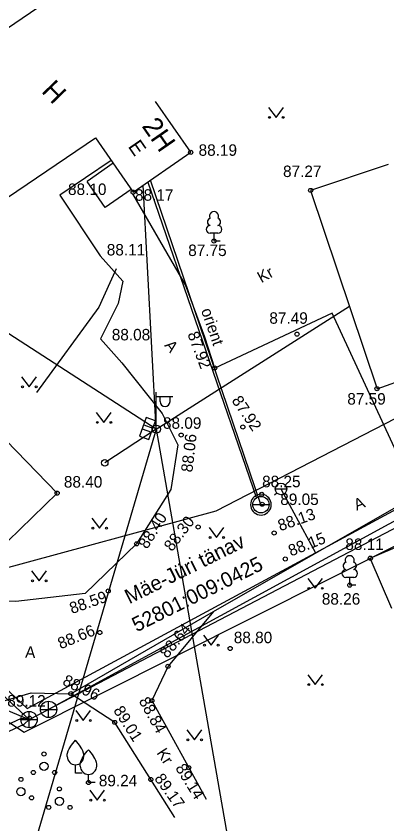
# Model space of a CAD drawing. Extents: x 648748 to 649126, y 6457789 to 6458252.
# Drawn here: x 649068.77 to 649091.37, y 6457945.81 to 6457995.06 of the extents above; entities that cross this region are included whole.
import ezdxf

# ---------------------------------------------------------------- set-up
doc = ezdxf.new("R2010")
doc.units = 0
for name, color, linetype in [('ELRAJATISMP', 7, 'Continuous'), ('HALJASTUS', 7, 'Continuous'), ('HOONE', 7, 'Continuous'), ('HOONEDET', 7, 'Continuous'), ('KKAEV', 7, 'Continuous'), ('KORGUS-EH2000', 7, 'Continuous'), ('KTRASS', 7, 'Continuous'), ('MPKAABEL', 7, 'Continuous'), ('MPOHULIIN', 7, 'Continuous'), ('PIIR', 7, 'Continuous'), ('POST', 7, 'Continuous'), ('PUU', 7, 'Continuous'), ('TEE', 7, 'Continuous'), ('VKAEV', 7, 'Continuous'), ('VTRASS', 7, 'Continuous')]:
    doc.layers.add(name, color=color, linetype=linetype)

msp = doc.modelspace()

# ---------------------------------------------------------------- linework, layer by layer
at = {"layer": 'ELRAJATISMP'}
for p, q in [((649076.706, 6457970.581), (649076.3, 6457969.457)), ((649077.268, 6457970.378), (649076.706, 6457970.581)), ((649076.861, 6457969.254), (649077.268, 6457970.378)), ((649076.457, 6457969.892), (649077.018, 6457969.689)), ((649076.549, 6457970.146), (649077.111, 6457969.943)), ((649076.3, 6457969.457), (649076.861, 6457969.254))]:
    msp.add_line(p, q, dxfattribs=at)
at = {"layer": 'HALJASTUS'}
for p, q in [((649084.161, 6457989.494), (649084.624, 6457988.888)), ((649084.624, 6457988.888), (649085.07, 6457989.494)), ((649069.102, 6457973.063), (649069.565, 6457972.457)), ((649069.565, 6457972.457), (649070.011, 6457973.063)), ((649073.66, 6457970.896), (649074.124, 6457970.29)), ((649074.124, 6457970.29), (649074.569, 6457970.896)), ((649073.394, 6457964.442), (649073.857, 6457963.835)), ((649073.857, 6457963.835), (649074.303, 6457964.442)), ((649080.531, 6457963.873), (649080.995, 6457963.266)), ((649080.995, 6457963.266), (649081.44, 6457963.873)), ((649069.706, 6457961.232), (649070.17, 6457960.626)), ((649070.17, 6457960.626), (649070.615, 6457961.232)), ((649086.548, 6457960.776), (649087.012, 6457960.17)), ((649087.012, 6457960.17), (649087.457, 6457960.776)), ((649080.196, 6457957.307), (649080.66, 6457956.7)), ((649080.66, 6457956.7), (649081.105, 6457957.307)), ((649086.548, 6457954.905), (649087.012, 6457954.298)), ((649087.012, 6457954.298), (649087.457, 6457954.905)), ((649072.403, 6457952.716), (649072.867, 6457952.11)), ((649072.867, 6457952.11), (649073.312, 6457952.716)), ((649079.182, 6457951.542), (649079.646, 6457950.935)), ((649079.646, 6457950.935), (649080.091, 6457951.542)), ((649073.257, 6457947.859), (649073.721, 6457947.252)), ((649073.721, 6457947.252), (649074.166, 6457947.859))]:
    msp.add_line(p, q, dxfattribs=at)
msp.add_lwpolyline([(649074.865, 6457979.646), (649073.818, 6457977.324), (649070.014, 6457972.105)], dxfattribs=at)
for centre in [(649084.223, 6457988.888), (649085.052, 6457988.888), (649069.164, 6457972.457), (649069.993, 6457972.457), (649073.723, 6457970.29), (649074.552, 6457970.29), (649073.456, 6457963.835), (649074.285, 6457963.835), (649080.594, 6457963.266), (649081.423, 6457963.266), (649069.769, 6457960.626), (649070.598, 6457960.626), (649086.611, 6457960.17), (649087.44, 6457960.17), (649080.259, 6457956.7), (649081.088, 6457956.7), (649086.611, 6457954.298), (649087.44, 6457954.298), (649072.466, 6457952.11), (649073.295, 6457952.11), (649079.245, 6457950.935), (649080.074, 6457950.935), (649073.32, 6457947.252), (649074.149, 6457947.252)]:
    msp.add_circle(centre, 0.055, dxfattribs=at)
at = {"layer": 'HOONE'}
for points in [[(649072.015, 6457996.882), (649063.446, 6457991.053), (649068.243, 6457984.001), (649073.604, 6457987.648), (649075.908, 6457984.326), (649079.415, 6457986.758), (649077.261, 6457989.865)], [(649091.46, 6457986.018), (649086.728, 6457984.435), (649090.775, 6457972.34), (649098.507, 6457975.105), (649096.333, 6457981.187)], [(649058.52, 6457968.558), (649063.804, 6457973.681), (649071.276, 6457965.976), (649065.991, 6457960.854), (649058.52, 6457968.558)], [(649091.683, 6457958.934), (649090.364, 6457962.006), (649093.978, 6457963.558), (649095.297, 6457960.486)]]:
    msp.add_lwpolyline(points, dxfattribs=at)
at = {"layer": 'HOONEDET'}
for p, q in [((649074.686, 6457986.087), (649073.096, 6457984.984)), ((649074.203, 6457983.387), (649073.096, 6457984.984)), ((649075.794, 6457984.49), (649074.203, 6457983.387))]:
    msp.add_line(p, q, dxfattribs=at)
at = {"layer": 'KKAEV'}
for p, q in [((649070.754, 6457952.286), (649070.754, 6457953.286)), ((649069.563, 6457951.663), (649069.563, 6457952.663)), ((649070.254, 6457952.786), (649071.254, 6457952.786)), ((649069.063, 6457952.163), (649070.063, 6457952.163))]:
    msp.add_line(p, q, dxfattribs=at)
for centre in [(649070.754, 6457952.786), (649069.563, 6457952.163)]:
    msp.add_circle(centre, 0.5, dxfattribs=at)
at = {"layer": 'KORGUS-EH2000'}
for centre in [(649079.415, 6457986.758), (649086.728, 6457984.435), (649075.908, 6457984.326), (649080.838, 6457981.344), (649085.896, 6457975.672), (649080.877, 6457973.605), (649090.775, 6457972.34), (649082.593, 6457970.01), (649078.835, 6457969.516), (649071.276, 6457965.976), (649083.748, 6457965.905), (649083.77, 6457965.298), (649079.871, 6457963.91), (649084.505, 6457963.542), (649076.118, 6457962.885), (649085.178, 6457961.959), (649090.364, 6457962.006), (649089.112, 6457960.362), (649074.389, 6457960.006), (649073.878, 6457957.474), (649081.822, 6457956.503), (649078.032, 6457955.416), (649072.111, 6457953.746), (649077.046, 6457953.323), (649069.586, 6457952.253), (649074.784, 6457951.992), (649079.298, 6457949.228), (649076.987, 6457948.512), (649073.186, 6457948.327)]:
    msp.add_circle(centre, 0.125, dxfattribs=at)
at = {"layer": 'KTRASS'}
for p, q in [((649044.701, 6457975.239), (649069.563, 6457952.163)), ((649069.563, 6457952.163), (649070.754, 6457952.786))]:
    msp.add_line(p, q, dxfattribs=at)
for points in [[(649110.189, 6457974.261), (649070.754, 6457952.786)], [(649096.029, 6457966.018), (649070.755, 6457952.79)], [(649051.71, 6457952.102), (649060.079, 6457956.155), (649069.563, 6457952.163)], [(649069.563, 6457952.163), (649069.086, 6457952.241), (649062.629, 6457949.241)], [(649062.797, 6457948.879), (649069.254, 6457951.879), (649069.563, 6457952.163)]]:
    msp.add_lwpolyline(points, dxfattribs=at)
at = {"layer": 'MPKAABEL'}
msp.add_line((649076.796, 6457984.942), (649083.432, 6457965.667), dxfattribs=at)
at = {"layer": 'MPOHULIIN'}
for q in [(649045.712, 6457990.322), (649076.524, 6457984.753), (649089.09, 6457977.375), (649069.137, 6457941.988), (649084.899, 6457926.464)]:
    msp.add_line((649077.318, 6457969.876), q, dxfattribs=at)
at = {"layer": 'PIIR'}
for p, q in [((649122.105, 6457986.094), (649080.95, 6457964.88)), ((649069.26, 6457951.39), (649125.584, 6457979.69)), ((649080.95, 6457964.88), (649065.03, 6457960.54)), ((649057.7, 6457959), (649069.26, 6457951.39))]:
    msp.add_line(p, q, dxfattribs=at)
at = {"layer": 'POST'}
for p, q in [((649077.318, 6457970.126), (649077.318, 6457972.126)), ((649077.318, 6457971.876), (649078.318, 6457971.876)), ((649077.545, 6457971.555), (649077.545, 6457971.876)), ((649078.158, 6457971.555), (649078.158, 6457971.876)), ((649077.318, 6457969.876), (649074.172, 6457967.817))]:
    msp.add_line(p, q, dxfattribs=at)
for centre, radius in [((649077.318, 6457969.876), 0.25), ((649074.172, 6457967.817), 0.2)]:
    msp.add_circle(centre, radius, dxfattribs=at)
msp.add_arc((649077.851, 6457971.555), 0.306, 180, 0, dxfattribs=at)
at = {"layer": 'PUU'}
for p, q in [((649081.078, 6457981.819), (649080.598, 6457981.819)), ((649080.838, 6457981.344), (649080.838, 6457981.819)), ((649081.218, 6457981.344), (649080.838, 6457981.344)), ((649089.352, 6457960.837), (649088.872, 6457960.837)), ((649089.112, 6457960.362), (649089.112, 6457960.837)), ((649089.492, 6457960.362), (649089.112, 6457960.362)), ((649072.393, 6457948.908), (649072.393, 6457949.408)), ((649072.793, 6457948.908), (649072.393, 6457948.908)), ((649073.186, 6457948.327), (649073.186, 6457948.827)), ((649073.586, 6457948.327), (649073.186, 6457948.327))]:
    msp.add_line(p, q, dxfattribs=at)
for points in [[(649071.893, 6457949.908), (649071.893, 6457950.058), (649071.903, 6457950.123), (649071.938, 6457950.253), (649071.998, 6457950.373), (649072.143, 6457950.608), (649072.303, 6457950.813), (649072.393, 6457950.908)], [(649072.893, 6457949.908), (649072.893, 6457950.058), (649072.883, 6457950.123), (649072.848, 6457950.253), (649072.788, 6457950.373), (649072.643, 6457950.608), (649072.483, 6457950.813), (649072.393, 6457950.908)], [(649072.686, 6457949.327), (649072.686, 6457949.477), (649072.696, 6457949.542), (649072.731, 6457949.672), (649072.791, 6457949.792), (649072.936, 6457950.027), (649073.096, 6457950.232), (649073.186, 6457950.327)], [(649073.686, 6457949.327), (649073.686, 6457949.477), (649073.676, 6457949.542), (649073.641, 6457949.672), (649073.581, 6457949.792), (649073.436, 6457950.027), (649073.276, 6457950.232), (649073.186, 6457950.327)]]:
    msp.add_lwpolyline(points, dxfattribs=at)
for centre, radius in [((649070.474, 6457950.067), 0.125), ((649070.474, 6457949.317), 0.25), ((649069.824, 6457948.942), 0.125), ((649071.124, 6457948.942), 0.125), ((649069.063, 6457948.519), 0.125), ((649069.063, 6457947.769), 0.25), ((649071.413, 6457947.936), 0.125), ((649069.713, 6457947.394), 0.125), ((649071.413, 6457947.186), 0.25), ((649070.763, 6457946.811), 0.125), ((649072.063, 6457946.811), 0.125)]:
    msp.add_circle(centre, radius, dxfattribs=at)
for centre, radius, start, end in [((649080.838, 6457982.864), 0.277, 332.58, 207.42), ((649080.668, 6457982.517), 0.233, 109.022, 253.142), ((649081.008, 6457982.517), 0.233, 286.851, 70.986), ((649080.601, 6457982.057), 0.238, 90.002, 269.395), ((649081.076, 6457982.057), 0.238, 270.605, 89.998), ((649089.112, 6457961.882), 0.277, 332.58, 207.42), ((649088.942, 6457961.535), 0.233, 109.022, 253.142), ((649089.282, 6457961.535), 0.233, 286.851, 70.986), ((649088.874, 6457961.075), 0.238, 90.002, 269.395), ((649089.349, 6457961.075), 0.238, 270.605, 89.998), ((649072.393, 6457949.908), 0.5, 180, 0), ((649073.186, 6457949.327), 0.5, 180, 0)]:
    msp.add_arc(centre, radius, start, end, dxfattribs=at)
at = {"layer": 'TEE'}
for points in [[(649073.892, 6457980.444), (649075.277, 6457978.898), (649074.998, 6457977.546), (649073.91, 6457975.39), (649075.219, 6457973.916), (649077.682, 6457970.841), (649078.634, 6457968.92), (649078.21, 6457966.199), (649076.118, 6457962.885), (649072.987, 6457959.848), (649068.76, 6457959.373), (649065.353, 6457959.385), (649062.208, 6457961.227), (649055.218, 6457967.101), (649039.374, 6457982.53), (649021.477, 6457999.638), (649003.487, 6458020.927), (649002.852, 6458022.042), (649010.237, 6458028.696), (649016.817, 6458021.893)], [(649024.176, 6457993.684), (649043.03, 6457975.251), (649059.66, 6457959.338), (649062.362, 6457955.934), (649067.734, 6457953.234), (649069.68, 6457953.796), (649072.111, 6457953.746), (649080.808, 6457958.747), (649093.109, 6457965.781), (649092.235, 6457967.901), (649088.043, 6457976.952), (649080.877, 6457973.605), (649080.278, 6457975.481), (649079.102, 6457978.684), (649075.883, 6457984.236)], [(649074.568, 6457986.256), (649071.44, 6457984.139), (649073.892, 6457980.444)], [(649080.808, 6457958.747), (649078.032, 6457955.416), (649077.046, 6457953.323), (649080.349, 6457947.317)], [(649078.453, 6457946.196), (649074.784, 6457951.992), (649072.111, 6457953.746)]]:
    msp.add_lwpolyline(points, dxfattribs=at)
at = {"layer": 'VKAEV'}
for p, q in [((649084.672, 6457965.983), (649084.532, 6457965.843)), ((649084.569, 6457966.23), (649085.269, 6457966.23)), ((649085.167, 6457965.983), (649085.306, 6457965.843)), ((649083.197, 6457965.273), (649084.197, 6457965.273))]:
    msp.add_line(p, q, dxfattribs=at)
msp.add_lwpolyline([(649084.329, 6457965.276), (649084.319, 6457965.386), (649084.29, 6457965.492), (649084.243, 6457965.592), (649084.179, 6457965.682), (649084.101, 6457965.759), (649084.01, 6457965.822), (649083.91, 6457965.868), (649083.803, 6457965.896), (649083.693, 6457965.905), (649083.584, 6457965.895), (649083.477, 6457965.866), (649083.378, 6457965.819), (649083.288, 6457965.755), (649083.21, 6457965.677), (649083.148, 6457965.586), (649083.102, 6457965.486), (649083.074, 6457965.379), (649083.065, 6457965.269), (649083.075, 6457965.16), (649083.104, 6457965.053), (649083.151, 6457964.954), (649083.215, 6457964.864), (649083.293, 6457964.786), (649083.384, 6457964.723), (649083.484, 6457964.677), (649083.591, 6457964.649), (649083.701, 6457964.64), (649083.81, 6457964.651), (649083.917, 6457964.68), (649084.016, 6457964.727), (649084.106, 6457964.791), (649084.184, 6457964.869), (649084.246, 6457964.96), (649084.292, 6457965.06), (649084.32, 6457965.166), (649084.329, 6457965.276)], dxfattribs=at)
for centre, radius in [((649084.919, 6457966.23), 0.35), ((649083.697, 6457965.273), 0.5)]:
    msp.add_circle(centre, radius, dxfattribs=at)
at = {"layer": 'VTRASS'}
msp.add_line((649083.697, 6457965.273), (649076.967, 6457985.06), dxfattribs=at)
for points in [[(648962.245, 6458064.485), (648962.49, 6458064.476), (648963.533, 6458062.388), (648984.937, 6458037.806), (648985.682, 6458036.975), (649020.474, 6457998.164), (649045.944, 6457974.832), (649068.737, 6457953.518), (649069.454, 6457952.848), (649087.021, 6457962.34), (649109.829, 6457974.665)], [(649084.92, 6457966.234), (649087.022, 6457962.344)]]:
    msp.add_lwpolyline(points, dxfattribs=at)

# ---------------------------------------------------------------- texts
at = {"layer": 'HOONE'}
for s, height, rotation, p in [('H', 1.2, 314.1017, (649070.264, 6457990.446)), ('2H', 1.2, 304.7389, (649076.403, 6457988.354)), ('E', 0.9, 304.7389, (649075.563, 6457987.114))]:
    msp.add_text(s, height=height, rotation=rotation, dxfattribs=at).set_placement(p)
at = {"layer": 'KORGUS-EH2000'}
for s, p in [('88.19', (649079.897, 6457986.545)), ('87.27', (649085.044, 6457985.25)), ('88.10', (649071.937, 6457984.156)), ('88.17', (649076.021, 6457983.804)), ('88.11', (649074.299, 6457980.467)), ('87.75', (649079.263, 6457980.434)), ('87.49', (649084.211, 6457976.303)), ('88.08', (649074.605, 6457975.289)), ('87.59', (649088.962, 6457971.374)), ('88.09', (649077.725, 6457969.899)), ('88.40', (649071.684, 6457966.314)), ('88.25', (649083.77, 6457966.334)), ('89.05', (649084.876, 6457965.251)), ('88.11', (649088.844, 6457962.509)), ('88.26', (649087.409, 6457959.176)), ('88.80', (649082.042, 6457956.824)), ('89.12', (649068.231, 6457952.958)), ('89.24', (649073.814, 6457948.096))]:
    msp.add_text(s, height=0.7, dxfattribs=at).set_placement(p)
for s, rotation, p in [('87.92', 290.6688, (649079.207, 6457975.679)), ('87.92', 304.3236, (649081.883, 6457971.62)), ('88.06', 83.4084, (649079.515, 6457967.221)), ('88.13', 19.2286, (649084.873, 6457963.648)), ('88.40', 57.7365, (649076.758, 6457962.52)), ('88.30', 52.7286, (649078.274, 6457962.372)), ('88.15', 21.3291, (649085.529, 6457962.11)), ('88.59', 19.3001, (649072.173, 6457958.598)), ('88.66', 22.3281, (649071.486, 6457956.449)), ('88.64', 50.1934, (649077.986, 6457955.857)), ('88.96', 334.2722, (649071.546, 6457954.317)), ('88.84', 298.8047, (649076.229, 6457953.308)), ('89.01', 302.3325, (649074.677, 6457952.729)), ('89.14', 301.7989, (649078.456, 6457949.209)), ('89.17', 305.4596, (649077.168, 6457948.573))]:
    msp.add_text(s, height=0.7, rotation=rotation, dxfattribs=at).set_placement(p)
at = {"layer": 'PIIR'}
for s, p in [('Mäe-Jüri tänav', (649075.678, 6457959.194)), ('52801:009:0425', (649076.119, 6457957.482))]:
    msp.add_text(s, height=0.9, rotation=26.4138, dxfattribs=at).set_placement(p)
at = {"layer": 'TEE'}
for s, rotation, p in [('Kr', 29.1383, (649083.721, 6457978.769)), ('A', 308.7048, (649077.775, 6457974.971)), ('A', 22.5526, (649089.534, 6457964.902)), ('A', 357.6183, (649069.313, 6457955.94)), ('Kr', 303.0854, (649077.309, 6457950.135))]:
    msp.add_text(s, height=0.7, rotation=rotation, dxfattribs=at).set_placement(p)
at = {"layer": 'VTRASS'}
msp.add_text('orient', height=0.7, rotation=289.0359, dxfattribs=at).set_placement((649080.037, 6457977.126))

doc.saveas('drawing.dxf')
